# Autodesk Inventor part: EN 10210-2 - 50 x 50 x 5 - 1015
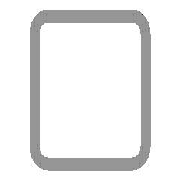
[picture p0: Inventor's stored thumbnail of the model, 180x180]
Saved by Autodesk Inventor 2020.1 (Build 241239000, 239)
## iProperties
IsCustomPart: 1
_CCFamilyMember: 16
_CCFamilyDisplayName: DIN EN 10210-2 (USAS B17.1 quadratisch) - Rohrleitung — In Klammern angegebene Größen wurden aufgehoben
_FrameMemberDoc: Frame Member File
_Version: 15.0.0
_GetPNFromCC: 1
Created: 2019-01
Part Number: EN 10210-2 - 50 x 50 x 5 - 1015
Material: Stahl, weich
Description: Rohrleitung
Document SubType Name: Modeling
Standard: DIN
Designer: lutzd
Standard Revision: 2006-07
Standards Organization: DIN
Language: de-DE
Size Designation: 50 x 50 x 5
Categories: <MemberInstance><Categories><Category DisplayName="Profile" InternalName="089c4875-fa83-4c05-b084-43b9cc11f5ed" Mnemonic="GRDR"><CategoryParameter DisplayName="
Stock Number: 50 x 50 x 5
Mass: 6957.24 g
Surface Area: 3453.64 cm^2
Volume: 886.272 cm^3
Density: 7.85 g/cm^3
Appearance: Halbpoliert
G_L: 1015,000 mm
G_W: 50,000 mm
G_H: 50,000 mm
DocNumber: ADSK-014085
Folder: .
Dimensions: 50x50x1015 mm
Mass: 6,957 kg
Title: Profil-Bauteil
Author: lutzd
Revision Number: -
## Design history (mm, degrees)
node "Startebene"
node "Endebene"
sketch "Skizze"
  geometry: L1 (-25, -17.5)-(-25, 17.5); L2 (-17.5, 25)-(17.5, 25); L3 (25, 17.5)-(25, -17.5); L4 (17.5, -25)-(-17.5, -25); L5 (-15, 20)-(15, 20); L6 (20, 15)-(20, -15); L7 (15, -20)-(-15, -20); L8 (-20, -15)-(-20, 15); L9 (0, 37.175)-(0, -37.175) reference; L10 (-37.175, 0)-(37.175, 0) reference; A1 r 7.5 centre (-17.5, -17.5) between (-25, -17.5) and (-17.5, -25); A2 r 7.5 centre (-17.5, 17.5) between (-17.5, 25) and (-25, 17.5); A3 r 7.5 centre (17.5, 17.5) between (25, 17.5) and (17.5, 25); A4 r 7.5 centre (17.5, -17.5) between (17.5, -25) and (25, -17.5); A5 r 5 centre (-15, -15) between (-20, -15) and (-15, -20); A6 r 5 centre (-15, 15) between (-15, 20) and (-20, 15); A7 r 5 centre (15, 15) between (20, 15) and (15, 20); A8 r 5 centre (15, -15) between (15, -20) and (20, -15)
  constraints: 16 end point, 16 point on circle, 16 tangent, 8 centre point, 6 equal radius, 4 parallel, 2 perpendicular, 2 other
  dimensions: "d7" = 7.5 radius of A1 (= G_IR); "d10" = 50 distance between parallel lines of L2 L4 (= G_H); "d11" = 50 distance between parallel lines of L1 L3 (= G_W); "d12" = 5 distance between parallel lines of L3 L6 (= G_T); "d15" = 25 distance between parallel lines of L2 L10 (= 0.5 x d10); "d16" = 25 distance between parallel lines of L9 L3 (= 0.5 x d11); "d19" = 5 radius of A5 (= G_T); "d20" = 5 distance between parallel lines of L4 L7 (= G_T)
extrude "Körper" new body sketch "Skizze" stored distance "d3" = 1015 (= G_L); taper "d4" = 0 deg
node "Driven Length"
  sketch "Sketch3"
    geometry: L1 (0, 0)-(10, 0) reference
    constraints: 2 end point, 1 horizontal
  workplane "Work Plane3"
  sketch "Sketch4"
    geometry: L1 (-2, 35)-(12, 35) reference; L2 (-2, 1050)-(12, 1050) reference
    dimensions: "d18" = 1015 distance between parallel lines of L1 L2 (derived)
body "Solid1"
other parameters: "G_W" = 50 [user parameter; used in 1 equation term], "G_H" = 50 [user parameter; used in 1 equation term], "G_T" = 5 [user parameter; used in 3 equation terms], "G_IR" = 7.5 [user parameter; used in 1 equation term], "G_L" = 1015 (= d18) [user parameter; used in 1 equation term], "G_OFFSET_START" = -35 [user parameter; used in 1 equation term], "G_OFFSET_END" = 0 [user parameter; used in 1 equation term], "d13" = 35 (= -G_OFFSET_START), "d17" = 90 deg
